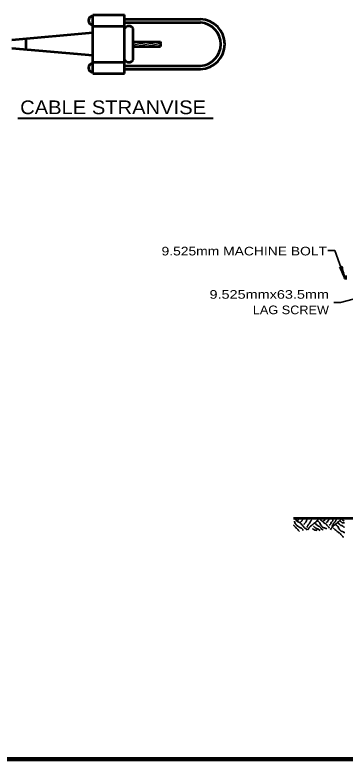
# Model space of a CAD drawing. Extents: x -34 to 821, y -14 to 530.
# Drawn here: x 257.5 to 373.2, y -2.2 to 258.7 of the extents above; entities that cross this region are included whole.
import ezdxf
from ezdxf.enums import TextEntityAlignment as Align

# ---------------------------------------------------------------- set-up
doc = ezdxf.new("R2010")
doc.units = 0
doc.header["$LTSCALE"] = 1.2
doc.layers.add('1', color=7, linetype='Continuous', lineweight=53)

msp = doc.modelspace()

# ---------------------------------------------------------------- linework, layer by layer
at = {"layer": '1'}
for p, q in [((284.707, 258.737), (295.915, 258.737)), ((284.707, 254.801), (284.707, 258.737)), ((295.915, 238.169), (295.915, 258.737)), ((295.915, 257.225), (322.507, 257.225)), ((295.915, 256.025), (322.507, 256.025)), ((284.707, 254.801), (295.915, 254.801)), ((298.939, 243.017), (298.939, 253.913)), ((284.707, 252.401), (256.387, 249.905)), ((261.235, 250.337), (261.235, 246.593)), ((298.939, 249.305), (308.419, 249.305)), ((284.707, 244.529), (256.387, 247.001)), ((298.939, 247.625), (308.419, 247.625)), ((284.707, 242.105), (295.915, 242.105)), ((295.915, 240.905), (322.507, 240.905)), ((284.707, 238.169), (295.915, 238.169)), ((295.915, 239.681), (322.507, 239.681)), ((373.775, 166.938), (372.887, 166.938)), ((372.887, 166.938), (372.887, 166.338)), ((373.775, 166.338), (372.887, 166.338)), ((355.079, 82.29), (581.063, 82.29))]:
    msp.add_line(p, q, dxfattribs=at)
at = {"layer": '1', "lineweight": 25}
for p, q in [((298.939, 247.625), (308.419, 249.305)), ((298.939, 248.849), (301.555, 249.305)), ((298.939, 248.225), (304.987, 249.305)), ((302.371, 247.625), (308.395, 248.705)), ((305.803, 247.625), (308.491, 248.105))]:
    msp.add_line(p, q, dxfattribs=at)
at = {"layer": '1', "lineweight": 40}
msp.add_line((258.524, 222.497), (326.971, 222.497), dxfattribs=at)
at = {"layer": '1', "lineweight": 158}
msp.add_line((814.88, -2.224), (23.28, -2.224), dxfattribs=at)
at = {"layer": '1'}
msp.add_lwpolyline([(284.707, 238.169), (284.707, 242.105), (284.707, 254.801)], dxfattribs=at)
at = {"layer": '1', "lineweight": 35}
for points in [[(372.839, 167.01), (369.527, 176.106), (367.103, 176.106)], [(380.927, 160.386), (371.591, 157.89), (369.167, 157.89)]]:
    msp.add_lwpolyline(points, dxfattribs=at)
at = {"layer": '1'}
for centre, radius, start, end in [((284.716, 256.778), 1.512, 90, 270), ((322.208, 248.462), 8.775, 272.01017, 87.98983), ((322.041, 248.462), 7.575, 273.59778, 86.40223), ((297.417, 253.099), 1.714, 28.07249, 151.92751), ((297.417, 243.824), 1.714, 208.07249, 331.92751), ((284.716, 240.146), 1.512, 90, 270)]:
    msp.add_arc(centre, radius, start, end, dxfattribs=at)
at = {"layer": '1', "lineweight": 40}
for centre, major_axis, ratio, start_param, end_param in [((372.067, 168.148), (0.916, -1.965), 0.122415, 0.8963533, 3.1415927), ((372.609, 168.383), (0.527, -2.069), 0.07063, 3.1407148, 5.41811)]:
    msp.add_ellipse(centre, major_axis=major_axis, ratio=ratio, start_param=start_param, end_param=end_param, dxfattribs=at)
at = {"layer": '1'}
msp.add_spline([(308.419, 249.305), (308.515, 249.137), (308.443, 249.041), (308.467, 248.849), (308.395, 248.705), (308.491, 248.561), (308.443, 248.441), (308.491, 248.225), (308.467, 248.057), (308.395, 247.913), (308.419, 247.841), (308.419, 247.625)], degree=3, dxfattribs=at)
at = {"layer": '1', "lineweight": 35}
for points in [[(355.367, 81.162), (355.535, 80.706), (355.847, 80.202), (356.231, 79.698), (356.615, 79.458), (357.263, 79.002), (358.319, 78.306), (358.343, 77.994)], [(355.631, 82.146), (356.423, 81.066), (357.431, 80.586), (358.031, 79.962), (358.343, 79.578), (358.727, 79.122), (359.039, 78.738), (359.519, 78.498), (359.903, 78.042)], [(357.023, 82.05), (356.927, 81.906), (356.879, 81.906), (356.807, 81.81), (356.615, 81.474), (356.567, 81.402)], [(358.463, 82.002), (358.223, 81.81), (358.151, 81.618), (358.079, 81.402), (357.935, 81.234), (357.839, 81.162), (357.503, 80.898)], [(359.975, 81.906), (359.735, 81.666), (359.591, 81.282), (359.399, 80.898), (358.967, 80.418), (358.823, 80.202), (358.727, 80.082)], [(361.487, 81.666), (361.127, 81.282), (360.935, 80.85), (360.623, 80.514), (360.407, 80.154), (360.167, 79.89), (360.047, 79.602), (359.903, 79.338), (359.711, 78.954)], [(363.815, 82.146), (363.815, 81.978), (363.719, 81.762), (363.575, 81.594), (363.431, 81.45), (363.119, 81.138), (362.879, 80.898), (362.183, 80.37), (361.799, 80.058), (361.031, 79.434), (360.719, 79.122), (360.551, 78.882), (360.335, 78.57), (360.095, 78.186)], [(363.575, 81.21), (363.815, 81.042), (364.031, 80.85), (364.463, 80.322), (364.511, 79.962), (364.823, 79.698), (364.919, 79.506), (365.711, 78.906), (366.167, 78.762), (366.287, 78.69), (366.719, 78.498)], [(364.079, 82.098), (364.703, 81.546), (365.231, 81.09), (366.167, 80.394), (366.407, 80.322), (366.623, 80.01), (367.007, 79.554), (367.487, 79.074), (367.703, 78.762)], [(365.471, 81.234), (366.023, 81.618), (366.119, 81.786), (366.311, 82.05)], [(366.503, 80.706), (366.935, 81.018), (367.223, 81.402), (367.295, 81.498), (367.439, 81.666), (367.679, 81.93)], [(367.511, 79.818), (368.063, 80.106), (368.135, 80.466), (368.639, 81.09), (368.807, 81.282), (368.879, 81.594), (368.903, 81.738)], [(371.711, 82.17), (371.711, 82.002), (371.639, 81.786), (371.471, 81.618), (371.327, 81.474), (371.015, 81.162), (370.775, 80.922), (370.079, 80.394), (369.695, 80.082), (368.927, 79.458), (368.615, 79.146), (368.471, 78.906), (368.231, 78.594), (367.991, 78.21)], [(370.319, 81.978), (369.959, 81.594), (369.767, 81.186), (369.455, 80.826), (369.239, 80.49), (368.999, 80.202), (368.879, 79.938), (368.735, 79.674), (368.543, 79.29)], [(371.399, 81.186), (371.663, 81.042), (372.167, 80.682), (372.239, 80.658), (372.479, 80.658), (372.983, 80.562)], [(372.119, 81.714), (372.263, 81.594), (372.263, 81.57), (372.335, 81.498), (372.695, 81.306), (372.767, 81.258)], [(355.055, 79.914), (355.223, 79.65), (355.535, 79.338), (355.919, 78.882), (356.255, 78.642), (356.567, 78.258), (356.879, 77.946), (357.191, 77.562)], [(361.727, 78.57), (361.991, 78.426), (362.495, 78.066), (362.567, 78.018), (362.807, 78.018), (363.311, 77.946)], [(362.063, 79.506), (362.567, 79.026), (362.759, 78.882), (363.119, 78.642), (363.815, 78.378), (364.031, 78.114), (364.391, 77.946)], [(362.807, 80.346), (363.383, 79.77), (363.503, 79.722), (363.623, 79.602), (364.127, 79.314), (364.727, 78.762), (364.919, 78.45), (365.519, 78.114)], [(368.975, 78.834), (369.575, 78.282), (370.127, 77.826), (371.063, 77.13), (371.279, 77.058), (371.519, 76.746), (371.903, 76.266), (372.383, 75.81), (372.599, 75.498)], [(369.935, 79.914), (370.175, 79.746), (370.391, 79.554), (370.823, 79.002), (370.871, 78.666), (371.183, 78.402), (371.279, 78.21), (372.071, 77.61), (372.527, 77.466), (372.647, 77.394), (373.079, 77.202)], [(370.631, 80.586), (371.135, 80.13), (371.327, 79.986), (371.663, 79.746), (372.359, 79.482), (372.599, 79.194), (372.935, 79.05)]]:
    msp.add_spline(points, degree=3, dxfattribs=at)

# ---------------------------------------------------------------- texts
at = {"layer": '1', "width": 1.1}
msp.add_text('CABLE STRANVISE', height=4.8, dxfattribs=at).set_placement((259.298, 223.928))
at = {"layer": '1'}
for s, width, p in [('9.525mm MACHINE BOLT', 1.2, (366.81, 174.392)), ('9.525mmx63.5mm', 1.25, (367.502, 159.21)), ('LAG SCREW', 1.1, (367.502, 153.786))]:
    msp.add_text(s, height=3.024, dxfattribs=dict(at, width=width)).set_placement(p, align=Align.RIGHT)

doc.saveas('drawing.dxf')
